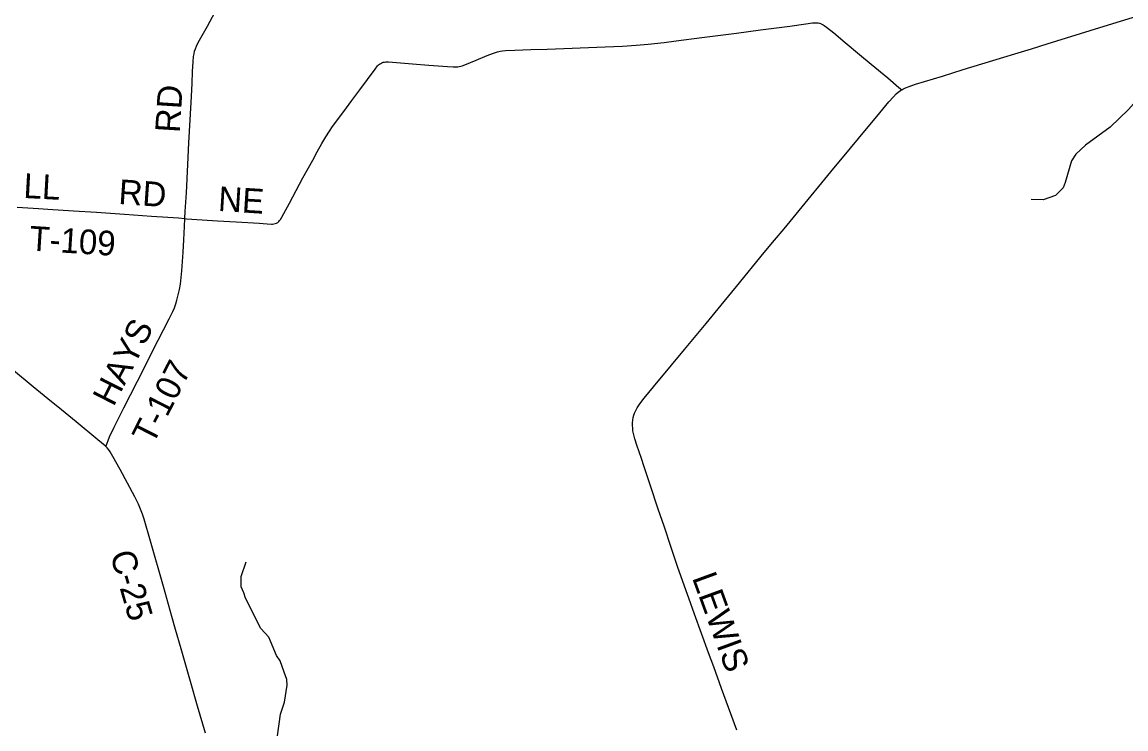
# Model space of a CAD drawing. Extents: x -51392 to 1635000, y 156707 to 696232.
# Drawn here: x 128704 to 142132, y 509767 to 518358 of the extents above; entities that cross this region are included whole.
import ezdxf

# ---------------------------------------------------------------- set-up
doc = ezdxf.new("R2010")
doc.units = 0
for name, color, linetype in [('GM_X_County_Road', 7, 'Continuous'), ('GM_X_County_Road_Text', 7, 'Continuous'), ('GM_X_Minor_River', 7, 'Continuous'), ('GM_X_Township_Road', 7, 'Continuous'), ('GM_X_Township_Road_Text', 7, 'Continuous')]:
    doc.layers.add(name, color=color, linetype=linetype)

msp = doc.modelspace()

# ---------------------------------------------------------------- linework, layer by layer
at = {"layer": 'GM_X_County_Road'}
for points in [[(139404, 517535), (139417, 517543), (139449, 517558), (139495, 517576), (139573, 517602), (139902, 517702), (140153, 517781), (140514, 517890), (140780, 517972), (140984, 518034), (141172, 518092), (141815, 518290), (142317, 518445), (142599, 518531), (143053, 518672), (143759, 518890), (144088, 518991), (144354, 519074), (144636, 519163), (145027, 519286), (145221, 519346), (145269, 519361)], [(137399, 509751), (137326, 509951), (137214, 510259), (137117, 510521), (137054, 510690), (136884, 511161), (136814, 511357), (136782, 511445), (136737, 511569), (136683, 511730), (136601, 511973), (136513, 512231), (136442, 512438), (136343, 512733), (136271, 512951), (136237, 513052), (136181, 513215), (136156, 513293), (136144, 513341), (136135, 513391), (136132, 513423), (136130, 513455), (136131, 513487), (136133, 513519), (136138, 513554), (136145, 513580), (136153, 513603), (136160, 513619), (136174, 513647), (136186, 513668), (136202, 513694), (136231, 513735), (136271, 513785), (136386, 513925), (136605, 514190), (136762, 514379), (137024, 514695), (137170, 514872), (137243, 514961), (137395, 515146), (137733, 515556), (137859, 515707), (137974, 515846), (138266, 516200), (138433, 516403), (138580, 516581), (138705, 516731), (138956, 517035), (139102, 517212), (139248, 517389), (139303, 517451), (139338, 517485), (139363, 517507), (139390, 517526), (139404, 517535)], [(129723, 513200), (129715, 513208), (129627, 513282), (129360, 513499), (129183, 513645), (129017, 513779), (128840, 513926), (128599, 514123), (128168, 514476), (127927, 514674), (127762, 514809), (127647, 514902), (127381, 515121), (127290, 515194)], [(130933, 509714), (130838, 510045), (130753, 510345), (130640, 510739), (130571, 510975), (130526, 511133), (130424, 511496), (130264, 512048), (130189, 512316), (130169, 512378), (130146, 512439), (130119, 512499), (130074, 512586), (129895, 512918), (129808, 513076), (129775, 513133), (129758, 513160), (129738, 513185), (129723, 513200)]]:
    msp.add_lwpolyline(points, dxfattribs=at)
at = {"layer": 'GM_X_Minor_River'}
for points in [[(144055, 518872), (143223, 518622), (143173, 518604), (143109, 518555), (143080, 518482), (143046, 518284), (143005, 518212), (142408, 517569), (142163, 517297), (141940, 517082), (141639, 516862), (141521, 516751), (141472, 516673), (141395, 516408), (141367, 516342), (141275, 516249), (141124, 516197), (140980, 516203)], [(131776, 509419), (131848, 509948), (131897, 510092), (131928, 510300), (131924, 510368), (131894, 510457), (131845, 510593), (131799, 510659), (131704, 510882), (131610, 510988), (131420, 511356), (131400, 511420), (131370, 511494), (131369, 511620), (131431, 511796)]]:
    msp.add_lwpolyline(points, dxfattribs=at)
at = {"layer": 'GM_X_Township_Road'}
for points in [[(130683, 515970), (130688, 516055), (130702, 516284), (130720, 516628), (130733, 516890), (130759, 517382), (130772, 517611), (130778, 517758), (130784, 517873), (130790, 517939), (130796, 517971), (130803, 518003), (130813, 518034), (130826, 518064), (130847, 518108), (130958, 518309), (131052, 518483), (131152, 518671), (131292, 518931), (131385, 519104), (131498, 519319)], [(130683, 515970), (130704, 515968), (130769, 515962), (131080, 515944), (131310, 515930), (131588, 515913), (131686, 515905), (131736, 515903), (131752, 515903), (131768, 515905), (131784, 515909), (131799, 515915), (131813, 515923), (131826, 515933), (131837, 515945), (131848, 515958), (131865, 515985), (131958, 516159), (132121, 516463), (132240, 516678), (132293, 516780), (132351, 516884), (132397, 516963), (132442, 517032), (132478, 517089), (132616, 517273), (132714, 517405), (132812, 517536), (132998, 517786), (133028, 517825), (133040, 517837), (133052, 517847), (133066, 517856), (133080, 517864), (133096, 517869), (133112, 517872), (133128, 517874), (133161, 517874), (133259, 517866), (133455, 517849), (133652, 517835), (133881, 517817), (133946, 517813), (133969, 517812), (133986, 517813), (134004, 517814), (134020, 517816), (134043, 517823), (134059, 517828), (134090, 517839), (134226, 517897), (134363, 517953), (134439, 517982), (134486, 517997), (134518, 518005), (134550, 518010), (134583, 518013), (134697, 518018), (134894, 518023), (135091, 518030), (135796, 518058), (136009, 518067), (136173, 518077), (136320, 518089), (136516, 518111), (136662, 518129), (136971, 518170), (137394, 518225), (137687, 518263), (138045, 518310), (138240, 518337), (138321, 518348), (138354, 518350), (138370, 518349), (138387, 518347), (138403, 518344), (138418, 518339), (138433, 518333), (138448, 518326), (138462, 518317), (138489, 518298), (138578, 518226), (138717, 518110), (138893, 517963), (139032, 517848), (139234, 517680), (139371, 517563), (139404, 517535)], [(128642, 516108), (128904, 516093), (129018, 516086), (129329, 516065), (129608, 516046), (129951, 516024), (130279, 516000), (130475, 515988), (130606, 515978), (130683, 515970)], [(129723, 513200), (129726, 513209), (129749, 513272), (129768, 513317), (129825, 513436), (129943, 513670), (130187, 514153), (130292, 514358), (130494, 514752), (130537, 514841), (130556, 514886), (130573, 514932), (130587, 514979), (130604, 515043), (130618, 515107), (130630, 515171), (130640, 515253), (130647, 515334), (130662, 515563), (130670, 515711), (130678, 515875), (130683, 515970)]]:
    msp.add_lwpolyline(points, dxfattribs=at)

# ---------------------------------------------------------------- texts
at = {"layer": 'GM_X_County_Road_Text'}
for s, rotation, p in [('C-25', 286.1539, (129771, 511891)), ('LEWIS', 290.0276, (136851, 511605))]:
    msp.add_text(s, height=300, rotation=rotation, dxfattribs=at).set_placement(p)
at = {"layer": 'GM_X_Township_Road_Text'}
for s, rotation, p in [('RD', 86.4535, (130622, 517007)), ('L', 356.9534, (128716, 516221)), ('L', 356.8462, (128940, 516209)), ('RD', 356.1057, (129871, 516148)), ('NE', 356.4156, (131083, 516063)), ('T-109', 356.3734, (128786, 515582)), ('HAYS', 63.1885, (129817, 513674)), ('T-107', 63.0945, (130296, 513209))]:
    msp.add_text(s, height=300, rotation=rotation, dxfattribs=at).set_placement(p)

doc.saveas('drawing.dxf')
